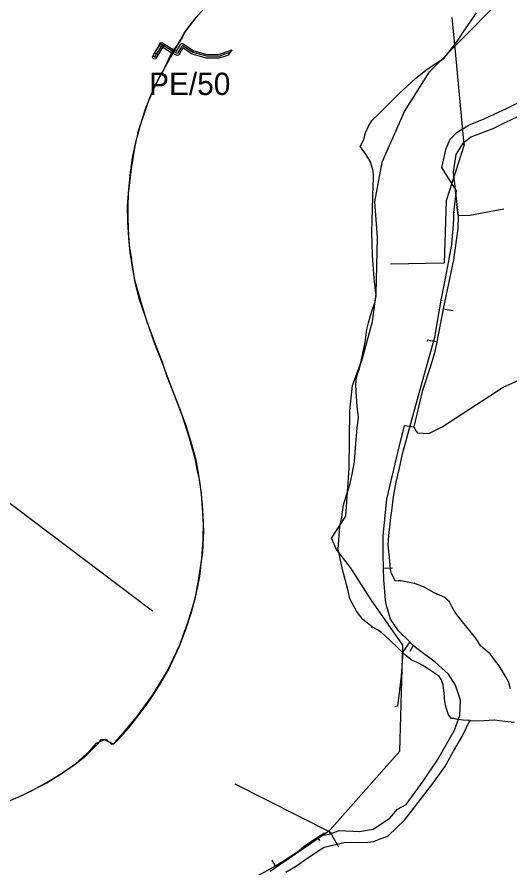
# Model space of a CAD drawing. Extents: x -555222 to -543220, y -1067119 to -1030889.
# Drawn here: x -550267 to -550001.7, y -1043311.9 to -1042854.2 of the extents above; entities that cross this region are included whole.
import ezdxf

# ---------------------------------------------------------------- set-up
doc = ezdxf.new("R2010")
doc.units = 0
for name, color, linetype in [('07_ELEKTRO', 7, 'Continuous'), ('07_KANALIZACE', 7, 'Continuous'), ('07_OCH_P A POPISY TI', 7, 'Continuous'), ('07_PLYNOVOD', 7, 'Continuous'), ('07_SDĚLOVACÍ', 7, 'Continuous'), ('07_VODOVOD', 7, 'Continuous')]:
    doc.layers.add(name, color=color, linetype=linetype)

msp = doc.modelspace()

# ---------------------------------------------------------------- linework, layer by layer
at = {"layer": '07_ELEKTRO'}
msp.add_lwpolyline([(-550194.01, -1043173.75), (-550276.86, -1043111.38), (-550319.34, -1043085.44), (-550353.72, -1043064.57), (-550404.37, -1043033.74), (-550454.56, -1043002.73), (-550510.03, -1042969.66), (-550549.39, -1042945.65), (-550716.81, -1043049.76), (-550814.42, -1043110.27), (-550908.37, -1043168.18), (-551001.8, -1043226.24), (-551078.24, -1043273.62), (-551121.4, -1043327.84), (-551166.14, -1043384.06), (-551153.41, -1043443.2), (-551142.16, -1043497.88), (-551075.2, -1043546.95)], dxfattribs=at)
at = {"layer": '07_KANALIZACE'}
msp.add_lwpolyline([(-550130.78, -1043313.61), (-550098.73, -1043291.61), (-550061.01, -1043248.96), (-550059.44, -1043191.98), (-550076.38, -1043167.65), (-550087.47, -1043150.2), (-550095.11, -1043140.58), (-550097.69, -1043134.44), (-550090.07, -1043122.66), (-550088.16, -1043096.85), (-550087.81, -1043065.85), (-550086.37, -1043052.29), (-550081.14, -1043037.92), (-550075.77, -1043018), (-550073.69, -1043003.11), (-550073, -1042972.84), (-550074.39, -1042953.53), (-550070.4, -1042932.18), (-550058.45, -1042905.03), (-550044.93, -1042883.73), (-550009.42, -1042847.76)], dxfattribs=at)
at = {"layer": '07_OCH_P A POPISY TI'}
for p, q in [((-550193.28, -1042874.2), (-550189.78, -1042868.63)), ((-550188.08, -1042869.69), (-550191.58, -1042875.26)), ((-550190.38, -1042869.02), (-550190.23, -1042868.63)), ((-550190.06, -1042869.78), (-550190.38, -1042869.02)), ((-550190.23, -1042868.63), (-550190.07, -1042868.25)), ((-550190.07, -1042868.25), (-550189.31, -1042867.93)), ((-550189.68, -1042869.94), (-550190.06, -1042869.78)), ((-550189.78, -1042868.63), (-550189.56, -1042868.28)), ((-550189.4, -1042870.05), (-550189.68, -1042869.94)), ((-550189.56, -1042868.28), (-550188.75, -1042868.09)), ((-550188.39, -1042870.74), (-550189.4, -1042870.05)), ((-550189.31, -1042867.93), (-550188.92, -1042868.08)), ((-550188.92, -1042868.08), (-550188.46, -1042868.27)), ((-550188.75, -1042868.09), (-550188.4, -1042868.31)), ((-550188.46, -1042868.27), (-550187.31, -1042869.04)), ((-550188.4, -1042868.31), (-550188.05, -1042868.53)), ((-550183.27, -1042873.78), (-550188.39, -1042870.74)), ((-550187.86, -1042869.34), (-550188.08, -1042869.69)), ((-550188.05, -1042868.53), (-550187.86, -1042869.34)), ((-550187.31, -1042869.04), (-550182.35, -1042872)), ((-550181.08, -1042872.57), (-550179, -1042868.92)), ((-550177.78, -1042870.83), (-550179.79, -1042874.35)), ((-550179, -1042868.92), (-550178.78, -1042868.55)), ((-550178.78, -1042868.55), (-550178.37, -1042868.45)), ((-550178.37, -1042868.45), (-550177.95, -1042868.35)), ((-550177.95, -1042868.35), (-550177.59, -1042868.58)), ((-550172.66, -1042874.13), (-550177.78, -1042870.83)), ((-550177.59, -1042868.58), (-550171.82, -1042872.29)), ((-550194.12, -1042875.54), (-550193.9, -1042875.19)), ((-550193.93, -1042876.35), (-550194.12, -1042875.54)), ((-550193.58, -1042876.57), (-550193.93, -1042876.35)), ((-550193.9, -1042875.19), (-550193.28, -1042874.2)), ((-550193.5, -1042874.55), (-550193.28, -1042874.2)), ((-550193.31, -1042875.36), (-550193.5, -1042874.55)), ((-550192.96, -1042875.58), (-550193.31, -1042875.36)), ((-550193.28, -1042874.2), (-550193.06, -1042873.85)), ((-550193.06, -1042873.85), (-550192.25, -1042873.66)), ((-550192.61, -1042875.8), (-550192.96, -1042875.58)), ((-550191.8, -1042875.62), (-550192.61, -1042875.8)), ((-550192.2, -1042876.25), (-550192.42, -1042876.6)), ((-550192.25, -1042873.66), (-550191.9, -1042873.88)), ((-550191.58, -1042875.26), (-550192.2, -1042876.25)), ((-550191.9, -1042873.88), (-550191.55, -1042874.1)), ((-550191.58, -1042875.26), (-550191.8, -1042875.62)), ((-550191.36, -1042874.91), (-550191.58, -1042875.26)), ((-550191.55, -1042874.1), (-550191.36, -1042874.91)), ((-550181.07, -1042874.76), (-550183.27, -1042873.78)), ((-550182.35, -1042872), (-550181.08, -1042872.57)), ((-550180.72, -1042874.92), (-550181.07, -1042874.76)), ((-550179.98, -1042874.68), (-550180.72, -1042874.92)), ((-550179.79, -1042874.35), (-550179.98, -1042874.68)), ((-550164.98, -1042876.3), (-550172.66, -1042874.13)), ((-550171.82, -1042872.29), (-550164.7, -1042874.3)), ((-550158.26, -1042876.38), (-550164.98, -1042876.3)), ((-550164.7, -1042874.3), (-550158.58, -1042874.38)), ((-550158.58, -1042874.38), (-550155.4, -1042873.28)), ((-550154.76, -1042875.18), (-550158.26, -1042876.38)), ((-550155.4, -1042873.28), (-550151.39, -1042871.92)), ((-550153.31, -1042874.68), (-550154.76, -1042875.18)), ((-550151.39, -1042871.92), (-550153.31, -1042874.68)), ((-550193.23, -1042876.79), (-550193.58, -1042876.57)), ((-550192.42, -1042876.6), (-550193.23, -1042876.79))]:
    msp.add_line(p, q, dxfattribs=at)
at = {"layer": '07_PLYNOVOD'}
for points in [[(-550188.93, -1042869.16), (-550192.43, -1042874.73)], [(-550152.35, -1042873.3), (-550155.08, -1042874.23), (-550158.42, -1042875.38), (-550164.84, -1042875.3), (-550172.24, -1042873.21), (-550178.13, -1042869.42), (-550180.66, -1042873.85), (-550182.81, -1042872.89), (-550187.85, -1042869.89), (-550188.93, -1042869.16), (-550189.3, -1042869.01)], [(-550192.43, -1042874.73), (-550193.05, -1042875.72)]]:
    msp.add_lwpolyline(points, dxfattribs=at)
at = {"layer": '07_SDĚLOVACÍ'}
for p, q in [((-550176.94, -1042862.92), (-550173.38, -1042858.11)), ((-550173.38, -1042858.11), (-550169.93, -1042853.72)), ((-550181.07, -1042870.1), (-550178.02, -1042865.55)), ((-550178.02, -1042865.55), (-550176.94, -1042862.92)), ((-550182.69, -1042872.02), (-550181.07, -1042870.1)), ((-550187.3, -1042880.99), (-550184.16, -1042874.41)), ((-550184.16, -1042874.41), (-550182.69, -1042872.02)), ((-550188.27, -1042883.35), (-550187.3, -1042880.99)), ((-550192.98, -1042891.66), (-550189.69, -1042885.21)), ((-550189.69, -1042885.21), (-550188.27, -1042883.35)), ((-550196.6, -1042900.52), (-550192.98, -1042891.66)), ((-550201.94, -1042916.54), (-550196.6, -1042900.52)), ((-550201.94, -1042916.54), (-550203.57, -1042923.56)), ((-550203.57, -1042923.56), (-550205.51, -1042935.77)), ((-550205.51, -1042935.77), (-550207.1, -1042949.24)), ((-550207.1, -1042949.24), (-550207.4, -1042956.01)), ((-550207.4, -1042956.01), (-550207.35, -1042962.78)), ((-550207.35, -1042962.78), (-550207.06, -1042972.24)), ((-550207.06, -1042972.24), (-550206.52, -1042978.5)), ((-550206.52, -1042978.5), (-550205.42, -1042983.98)), ((-550203.49, -1042995.76), (-550205.42, -1042983.98)), ((-550199.68, -1043009.52), (-550203.49, -1042995.76)), ((-550196.56, -1043019.25), (-550199.68, -1043009.52)), ((-550193.53, -1043027.29), (-550196.56, -1043019.25)), ((-550188.85, -1043039.42), (-550193.63, -1043027.15)), ((-550186.16, -1043047.55), (-550188.85, -1043039.42)), ((-550182, -1043058.04), (-550186.16, -1043047.55)), ((-550177.84, -1043068.95), (-550182, -1043058.04)), ((-550174.26, -1043080.24), (-550177.84, -1043068.95)), ((-550171.03, -1043091.67), (-550174.26, -1043080.24)), ((-550169.89, -1043098.48), (-550171.03, -1043091.67)), ((-550168.82, -1043102.79), (-550169.89, -1043098.48)), ((-550167.62, -1043110.38), (-550168.82, -1043102.79)), ((-550166.92, -1043120.85), (-550167.62, -1043110.38)), ((-550166.46, -1043130.3), (-550166.92, -1043120.85)), ((-550166.9, -1043141.98), (-550166.46, -1043130.3)), ((-550169.18, -1043156.15), (-550166.9, -1043141.98)), ((-550171.16, -1043167.19), (-550169.18, -1043156.15)), ((-550174.96, -1043179.27), (-550171.16, -1043167.19)), ((-550179.44, -1043191.83), (-550174.96, -1043179.27)), ((-550186.08, -1043205.77), (-550179.44, -1043191.83)), ((-550193.89, -1043218.78), (-550186.08, -1043205.77)), ((-550202.53, -1043230.54), (-550193.89, -1043218.78)), ((-550208.73, -1043237.92), (-550202.53, -1043230.54)), ((-550214.37, -1043244.19), (-550208.73, -1043237.92)), ((-550228.98, -1043250.58), (-550223.32, -1043244.86)), ((-550223.32, -1043244.86), (-550221.7, -1043242.8)), ((-550221.7, -1043242.8), (-550220.04, -1043242.72)), ((-550220.04, -1043242.72), (-550215.24, -1043245.06)), ((-550215.24, -1043245.06), (-550214.37, -1043244.19)), ((-550237.06, -1043257.15), (-550229.93, -1043251.63)), ((-550229.93, -1043251.63), (-550228.98, -1043250.58)), ((-550250.86, -1043266.16), (-550237.06, -1043257.15)), ((-550263.93, -1043272.75), (-550250.86, -1043266.16)), ((-550274.39, -1043277.25), (-550263.93, -1043272.75))]:
    msp.add_line(p, q, dxfattribs=at)
for points in [[(-550267.99, -1043274.47), (-550259.58, -1043270.5), (-550251.06, -1043265.88), (-550243.2, -1043261.29), (-550235.26, -1043255.65), (-550228.03, -1043249.13), (-550224.14, -1043244.78), (-550219.3, -1043242.56), (-550218.84, -1043242.7), (-550216.14, -1043245.22), (-550214.94, -1043245.17), (-550212.57, -1043242.94), (-550206.94, -1043236.63), (-550201.24, -1043229.29), (-550195.54, -1043221.57), (-550190.34, -1043213.62), (-550185.54, -1043205.22), (-550183.18, -1043200.3), (-550179.66, -1043192.84), (-550176.13, -1043183.62), (-550173.05, -1043174.33), (-550170.54, -1043164.69), (-550168.63, -1043155.11), (-550167.43, -1043145.31), (-550166.79, -1043135.48), (-550166.7, -1043125.62), (-550167.09, -1043116.55), (-550167.96, -1043109.37), (-550169.11, -1043100.56), (-550170.57, -1043092.37), (-550172.9, -1043084.19), (-550175.84, -1043074.65), (-550179.02, -1043065.88), (-550182.38, -1043056.95), (-550185.94, -1043047.66), (-550189.28, -1043038.93), (-550192.81, -1043029.93), (-550196.1, -1043020.66), (-550199.34, -1043011.31), (-550201.08, -1043006.03), (-550203.21, -1042997.68), (-550204.84, -1042988.68), (-550206.11, -1042980.85), (-550206.85, -1042973.17), (-550207.42, -1042964.43), (-550207.45, -1042955.57), (-550206.79, -1042946.92), (-550205.94, -1042937.79), (-550204.76, -1042929.93), (-550203.02, -1042921.44), (-550200.62, -1042912.9), (-550197.81, -1042903.49), (-550194.44, -1042894.89), (-550190.48, -1042887.09), (-550185.91, -1042878.8), (-550181.3, -1042870.51), (-550176.23, -1042861.96), (-550170.64, -1042854.42), (-550165.11, -1042848.29)], [(-550026.37, -1042922.96), (-550030.84, -1042874.78), (-550032.76, -1042854.4)], [(-549952.71, -1042893.77), (-549962.92, -1042894.69), (-549970.24, -1042896.24), (-549982.77, -1042900.87), (-550004.17, -1042910.85), (-550010.54, -1042914.14), (-550022.78, -1042918.72), (-550027.18, -1042922.37)], [(-550004.17, -1042910.85), (-550010.54, -1042914.14)], [(-550026.37, -1042922.96), (-550035.99, -1042953.03), (-550037.2, -1042986.64), (-550065.99, -1042987.08)], [(-550027.18, -1042922.37), (-550030.92, -1042928.12), (-550032.36, -1042937.57), (-550030.35, -1042954.96), (-550029.66, -1042960.92)], [(-550026.37, -1042922.96), (-550027.18, -1042922.37)], [(-550029.66, -1042960.92), (-550030.35, -1042954.96)], [(-550029.66, -1042960.92), (-550023.24, -1042960.7), (-550004.94, -1042957.35)], [(-550029.66, -1042960.92), (-550029.85, -1042968.01), (-550032.1, -1042984.79), (-550037.7, -1043011.07)], [(-550037.7, -1043011.07), (-550041.14, -1043028.81)], [(-550037.7, -1043011.07), (-550032.31, -1043012.11)], [(-550041.14, -1043028.81), (-550042.26, -1043034.81), (-550044.32, -1043041.47), (-550048.88, -1043055.61), (-550053.48, -1043074.61)], [(-550041.14, -1043028.81), (-550044.43, -1043028.29), (-550046.17, -1043027.94), (-550046.37, -1043028.76)], [(-550041.14, -1043028.81), (-550044.43, -1043028.29)], [(-550042.26, -1043034.81), (-550044.32, -1043041.47)], [(-550038.21, -1043074.56), (-550005.46, -1043053.23), (-549964.22, -1043035), (-549922.99, -1043060.58)], [(-550062.08, -1043088.43), (-550058.42, -1043073.96)], [(-550058.42, -1043073.96), (-550053.48, -1043074.61)], [(-550058.42, -1043073.96), (-550053.48, -1043074.61)], [(-550053.48, -1043074.61), (-550052.11, -1043076.85), (-550051.53, -1043077.8), (-550045.46, -1043078.12), (-550038.21, -1043074.56)], [(-550069.7, -1043150.64), (-550070, -1043142.73), (-550069.88, -1043133), (-550068.01, -1043113.56), (-550062.08, -1043088.43)], [(-550069.7, -1043150.64), (-550064.99, -1043150.52)], [(-550069.7, -1043150.64), (-550064.99, -1043150.52)], [(-550055.65, -1043190.31), (-550061.69, -1043184.35), (-550065.93, -1043177.97), (-550068.14, -1043170.67), (-550068.67, -1043167.78), (-550069.58, -1043156.73), (-550069.7, -1043150.64)], [(-550068.67, -1043167.78), (-550069.58, -1043156.73)], [(-550055.65, -1043190.31), (-550061.69, -1043184.35), (-550065.93, -1043177.97)], [(-550055.65, -1043190.31), (-550059.35, -1043195.66), (-550060.32, -1043208.79), (-550062.24, -1043224.84), (-550063.75, -1043225.25)], [(-550055.04, -1043191), (-550055.65, -1043190.31)], [(-550053.84, -1043192.19), (-550055.53, -1043195.44)], [(-550053.84, -1043192.19), (-550055.04, -1043191)], [(-550051.88, -1043193.85), (-550053.84, -1043192.19)], [(-550042.04, -1043201.19), (-550051.88, -1043193.85)], [(-550098.41, -1043293.53), (-550093.7, -1043291.69), (-550082.76, -1043292.26), (-550075.3, -1043291.01), (-550066.27, -1043285.09), (-550062.3, -1043280.2), (-550057.58, -1043277.71), (-550048.51, -1043265.09), (-550040.34, -1043253.24), (-550031.57, -1043237.82), (-550028.71, -1043229.91), (-550028.41, -1043221.53), (-550031.02, -1043213.52), (-550034.84, -1043207.7), (-550042.04, -1043201.19)], [(-550057.58, -1043277.71), (-550048.51, -1043265.09), (-550040.34, -1043253.24), (-550031.57, -1043237.82), (-550028.71, -1043229.91), (-550028.41, -1043221.53), (-550031.02, -1043213.52), (-550034.84, -1043207.7)], [(-550098.51, -1043292.69), (-550149.56, -1043266.77)], [(-550098.41, -1043293.53), (-550098.51, -1043292.69)], [(-550098.51, -1043292.69), (-550094.07, -1043300.42)], [(-550127.84, -1043310.69), (-550123.63, -1043307.98), (-550116.08, -1043303.15), (-550111.8, -1043299.68), (-550104.35, -1043294.72), (-550098.41, -1043293.53)], [(-550123.63, -1043307.98), (-550116.08, -1043303.15), (-550111.8, -1043299.68), (-550104.35, -1043294.72), (-550098.41, -1043293.53)], [(-550138.82, -1043316.27), (-550138.17, -1043316.46), (-550127.84, -1043310.69)], [(-550127.84, -1043310.69), (-550129.65, -1043307.93), (-550129.25, -1043307.65)]]:
    msp.add_lwpolyline(points, dxfattribs=at)
at = {"layer": '07_VODOVOD'}
for p, q in [((-550075.41, -1042937.08), (-550075.66, -1042937.07)), ((-550075.41, -1042937.08), (-550075.66, -1042937.07)), ((-550031.89, -1042959.25), (-550031.46, -1042959.21)), ((-550074.55, -1042996.55), (-550074.71, -1042996.61)), ((-550038.65, -1043006.43), (-550038.12, -1043006.56)), ((-550084.41, -1043057.17), (-550084.54, -1043057.19)), ((-550053.09, -1043158.93), (-550052.97, -1043158.35)), ((-550075.79, -1043182.09), (-550076.2, -1043182.87)), ((-550035.84, -1043226.25), (-550035.91, -1043226.45)), ((-550105.21, -1043295.36), (-550101.46, -1043292.93)), ((-550104.04, -1043297.03), (-550105.21, -1043295.36))]:
    msp.add_line(p, q, dxfattribs=at)
for points in [[(-550122.28, -1043314.2), (-550117.09, -1043311.16), (-550112.2, -1043307.75), (-550107.32, -1043304.34), (-550104.55, -1043302.54), (-550101.78, -1043300.74), (-550090.25, -1043297.9), (-550083.45, -1043298.11), (-550078.28, -1043298.06), (-550074.97, -1043297.56), (-550071.5, -1043296.28), (-550068.04, -1043295), (-550066.99, -1043294.47), (-550062.72, -1043290.27), (-550058.46, -1043286.07), (-550054.76, -1043281.38), (-550051.05, -1043276.68), (-550043.71, -1043267.19), (-550036.74, -1043257.47), (-550032.02, -1043249.1), (-550027.31, -1043240.73), (-550023.28, -1043232.52), (-550023.92, -1043232.51), (-550026.94, -1043232.28), (-550029.96, -1043232.04), (-550031.92, -1043231.52), (-550033.15, -1043231.4), (-550034.77, -1043229.46), (-550035.3, -1043227.86), (-550035.84, -1043226.25), (-550036.34, -1043224.25), (-550036.84, -1043222.25), (-550037.02, -1043220.25), (-550037.09, -1043217.79), (-550037.58, -1043213.42), (-550038.34, -1043211.31), (-550038.81, -1043210.46), (-550039.28, -1043209.6), (-550039.82, -1043208.88), (-550041.76, -1043207.48), (-550043.92, -1043206.03), (-550046.08, -1043204.58), (-550048.59, -1043203.01), (-550050.28, -1043202.08), (-550051.96, -1043201.14), (-550054.69, -1043200.11), (-550056.1, -1043198.9), (-550057.52, -1043197.7), (-550061.97, -1043193.46), (-550066.25, -1043189.45), (-550070.93, -1043185.28), (-550073.36, -1043183.68), (-550075.79, -1043182.09), (-550078.32, -1043180.17), (-550080.85, -1043178.25), (-550082.55, -1043176), (-550084.25, -1043173.76), (-550087.96, -1043167.08), (-550088.82, -1043162.86), (-550091.75, -1043151.25), (-550094.08, -1043140.46), (-550093.18, -1043128.2), (-550092.19, -1043123.1), (-550091.25, -1043116.55), (-550089.86, -1043111.82), (-550087.75, -1043105.06), (-550087.16, -1043102.56), (-550086.57, -1043100.06), (-550085.38, -1043093.35), (-550085.06, -1043088.2), (-550084.56, -1043081.41), (-550083.92, -1043075.4), (-550083.27, -1043069.39), (-550083.83, -1043065.28), (-550084.1, -1043061.36), (-550084.37, -1043057.43), (-550084.41, -1043057.17), (-550084.55, -1043054.85), (-550084.69, -1043052.53), (-550084.53, -1043049.34), (-550083.61, -1043045.69), (-550082.64, -1043043.22), (-550081.9, -1043040.32), (-550080.74, -1043034.13), (-550079.58, -1043029.22), (-550078.74, -1043022.29), (-550077.77, -1043018.61), (-550076.68, -1043014.7), (-550075.59, -1043010.79), (-550074.22, -1043007.61), (-550073.8, -1043003.9), (-550074.02, -1043001.5), (-550074.24, -1042999.09), (-550074.4, -1042997.82), (-550074.55, -1042996.55), (-550074.74, -1042994.54), (-550074.93, -1042992.52), (-550075.16, -1042989.88), (-550075.39, -1042987.24), (-550075.69, -1042982.46), (-550075.88, -1042975.27), (-550076.08, -1042970.37), (-550075.89, -1042963.21), (-550075.49, -1042951.2), (-550075.28, -1042944.5), (-550075.23, -1042941.84), (-550075.18, -1042939.19), (-550075.41, -1042937.08), (-550075.53, -1042936.35), (-550076.85, -1042932.16), (-550079.32, -1042928.02), (-550080.78, -1042925.96), (-550082.24, -1042923.89), (-550081.28, -1042921.89), (-550080.33, -1042919.89), (-550079.48, -1042916.43), (-550077.79, -1042912.85), (-550075.81, -1042909.75), (-550072.82, -1042906.76), (-550069.82, -1042903.77), (-550065.66, -1042899.63), (-550061.49, -1042895.49), (-550057.06, -1042891.35), (-550052.63, -1042887.21), (-550047.04, -1042882.71), (-550043.08, -1042880.1), (-550037.21, -1042876.28), (-550035.91, -1042874.78), (-550032.88, -1042870.76), (-550029.85, -1042866.74), (-550026.46, -1042861.85), (-550023.08, -1042856.96), (-550019.75, -1042851.93)], [(-550001.47, -1043215.59), (-550002.59, -1043211.56), (-550005.06, -1043207.34), (-550007.52, -1043203.12), (-550009.95, -1043199.89), (-550012.38, -1043196.66), (-550014.98, -1043194.56), (-550017.57, -1043192.46), (-550018.88, -1043190.3), (-550020.18, -1043188.15), (-550021.72, -1043186.26), (-550023.26, -1043184.36), (-550027.25, -1043179.42), (-550031.24, -1043174.48), (-550032.76, -1043171.64), (-550034.27, -1043168.79), (-550035.53, -1043167.61), (-550036.79, -1043166.43), (-550039.66, -1043165.17), (-550042.52, -1043163.91), (-550045.38, -1043162.26), (-550048.23, -1043160.62), (-550050.66, -1043159.78), (-550053.09, -1043158.93), (-550056.77, -1043158.18), (-550060.45, -1043157.42), (-550061.93, -1043157.48), (-550063.41, -1043157.55), (-550064.44, -1043155.48), (-550065.46, -1043153.41), (-550066.03, -1043151.36), (-550066.6, -1043144.7), (-550067.17, -1043138.03), (-550066.84, -1043133.08), (-550066.21, -1043126.85), (-550065.79, -1043123.28), (-550065.37, -1043119.72), (-550064.46, -1043112.22), (-550062.94, -1043104.38), (-550061.22, -1043096.77), (-550059.5, -1043089.16), (-550050.86, -1043057.73), (-550042.22, -1043026.3), (-550038.65, -1043006.43), (-550036.42, -1042994.88), (-550034.18, -1042983.32), (-550032.98, -1042976.6), (-550032.58, -1042971.96), (-550032.07, -1042966), (-550031.98, -1042962.63), (-550031.89, -1042959.25), (-550031.15, -1042953.49), (-550030.41, -1042947.74), (-550034.43, -1042941.42), (-550038.46, -1042935.11), (-550036.08, -1042924.94), (-550033.87, -1042919.9), (-550030.3, -1042916.37), (-550023.6, -1042912.24), (-550015.99, -1042909.07), (-550009.81, -1042906.22), (-550003.63, -1042903.37), (-549990.12, -1042896.61)], [(-550023.28, -1043232.52), (-550022.6, -1043232.58), (-550021.31, -1043232.74), (-550015.78, -1043232.48), (-550010.26, -1043232.21), (-550010, -1043232.22), (-550004.62, -1043232.85), (-549999.24, -1043233.48)]]:
    msp.add_lwpolyline(points, dxfattribs=at)

# ---------------------------------------------------------------- texts
at = {"layer": '07_OCH_P A POPISY TI'}
msp.add_text('PE/50', height=12, dxfattribs=at).set_placement((-550195.88, -1042896.13))

doc.saveas('drawing.dxf')
